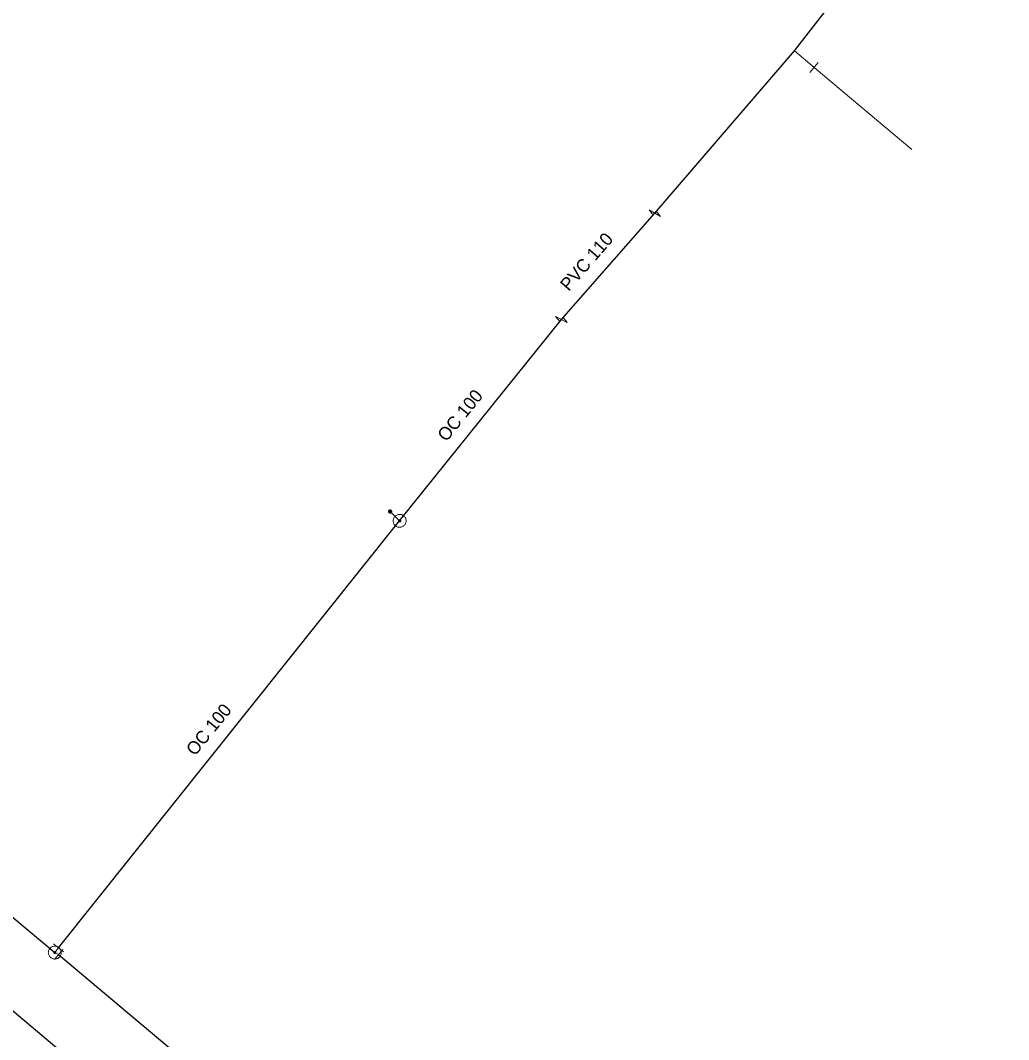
# Model space of a CAD drawing. Extents: x -790267 to -789874, y -989766 to -989454.
# Drawn here: x -790179 to -790102.5, y -989612.1 to -989533.1 of the extents above; entities that cross this region are included whole.
import ezdxf

# ---------------------------------------------------------------- set-up
doc = ezdxf.new("R2010")
doc.units = 0
doc.header["$LTSCALE"] = 0.4
doc.layers.add('1', color=7, linetype='Continuous')
for name, color, linetype, lineweight in [('13', 7, 'Continuous', 13), ('14', 7, 'Continuous', 13), ('17', 7, 'Continuous', 25), ('34', 7, 'Continuous', 13), ('47', 7, 'Continuous', 13), ('9', 7, 'Continuous', 13)]:
    doc.layers.add(name, color=color, linetype=linetype, lineweight=lineweight)

msp = doc.modelspace()

# ---------------------------------------------------------------- linework, layer by layer
at = {"layer": '13'}
msp.add_line((-790117.526, -989536.763), (-790109.967, -989543.114), dxfattribs=at)
at = {"layer": '14'}
for p, q in [((-790119.05, -989535.482), (-790117.526, -989536.763)), ((-790149.607, -989571.88), (-790150.346, -989571.155)), ((-790176.007, -989604.944), (-790176.305, -989605.314)), ((-790176.305, -989605.314), (-790176.006, -989605.454))]:
    msp.add_line(p, q, dxfattribs=at)
at = {"layer": '14', "lineweight": 25}
msp.add_lwpolyline([(-790061.947, -989710.475), (-790095.515, -989680.27), (-790099.671, -989676.98), (-790135.954, -989646.924), (-790158.92, -989627.239), (-790187.694, -989603.019)], dxfattribs=at)
at = {"layer": '17'}
for p, q in [((-790176.007, -989604.944), (-790149.607, -989571.88)), ((-790208.807, -989578.056), (-790176.305, -989605.314))]:
    msp.add_line(p, q, dxfattribs=at)
for points in [[(-790129.848, -989548.061), (-790119.05, -989535.482), (-790055.819, -989454.186)], [(-790149.607, -989571.88), (-790137.084, -989556.289), (-790129.848, -989548.061)], [(-790176.006, -989605.454), (-790166.475, -989613.482), (-790103.748, -989666.305)]]:
    msp.add_lwpolyline(points, dxfattribs=at)
at = {"layer": '34'}
for p, q in [((-790117.204, -989536.379), (-790117.848, -989537.145)), ((-790176.394, -989604.628), (-790175.62, -989605.26)), ((-790176.321, -989605.841), (-790175.689, -989605.067))]:
    msp.add_line(p, q, dxfattribs=at)
at = {"layer": '47'}
for p, q in [((-790130.288, -989547.804), (-790129.98, -989548.211)), ((-790137.535, -989556.052), (-790137.209, -989556.445))]:
    msp.add_line(p, q, dxfattribs=at)
for points in [[(-790130.288, -989547.804), (-790129.407, -989548.317), (-790129.715, -989547.91)], [(-790137.535, -989556.052), (-790136.632, -989556.525), (-790136.958, -989556.132)]]:
    msp.add_lwpolyline(points, dxfattribs=at)
for points in [[(-790149.288, -989571.494), (-790149.33, -989571.463), (-790149.375, -989571.436), (-790149.423, -989571.415), (-790149.472, -989571.398), (-790149.524, -989571.386), (-790149.576, -989571.381), (-790149.628, -989571.381), (-790149.68, -989571.386), (-790149.731, -989571.396), (-790149.781, -989571.411), (-790149.83, -989571.432), (-790149.875, -989571.458), (-790149.917, -989571.488), (-790149.957, -989571.523), (-790149.992, -989571.561), (-790150.023, -989571.603), (-790150.05, -989571.648), (-790150.071, -989571.697), (-790150.088, -989571.745), (-790150.1, -989571.797), (-790150.105, -989571.849), (-790150.106, -989571.902), (-790150.101, -989571.954), (-790150.091, -989572.005), (-790150.075, -989572.054), (-790150.054, -989572.103), (-790150.028, -989572.148), (-790149.998, -989572.19), (-790149.963, -989572.23), (-790149.925, -989572.265), (-790149.883, -989572.296), (-790149.838, -989572.323), (-790149.79, -989572.345), (-790149.741, -989572.361), (-790149.689, -989572.373), (-790149.638, -989572.379), (-790149.585, -989572.38), (-790149.533, -989572.375), (-790149.481, -989572.364), (-790149.432, -989572.348), (-790149.383, -989572.327), (-790149.338, -989572.302), (-790149.296, -989572.271), (-790149.256, -989572.236), (-790149.221, -989572.198), (-790149.19, -989572.156), (-790149.163, -989572.111), (-790149.141, -989572.064), (-790149.125, -989572.014), (-790149.113, -989571.962), (-790149.107, -989571.911), (-790149.107, -989571.859), (-790149.112, -989571.807), (-790149.123, -989571.755), (-790149.138, -989571.705), (-790149.159, -989571.656), (-790149.185, -989571.612), (-790149.215, -989571.569), (-790149.25, -989571.529)], [(-790149.554, -989571.816), (-790149.561, -989571.811), (-790149.569, -989571.807), (-790149.576, -989571.803), (-790149.584, -989571.801), (-790149.593, -989571.799), (-790149.601, -989571.798), (-790149.61, -989571.797), (-790149.619, -989571.798), (-790149.627, -989571.8), (-790149.635, -989571.803), (-790149.643, -989571.806), (-790149.651, -989571.811), (-790149.657, -989571.815), (-790149.664, -989571.82), (-790149.67, -989571.827), (-790149.675, -989571.834), (-790149.679, -989571.842), (-790149.683, -989571.849), (-790149.685, -989571.857), (-790149.687, -989571.866), (-790149.688, -989571.874), (-790149.689, -989571.883), (-790149.688, -989571.892), (-790149.686, -989571.901), (-790149.683, -989571.908), (-790149.68, -989571.916), (-790149.675, -989571.924), (-790149.671, -989571.93), (-790149.666, -989571.937), (-790149.659, -989571.943), (-790149.652, -989571.948), (-790149.644, -989571.952), (-790149.637, -989571.956), (-790149.629, -989571.958), (-790149.62, -989571.96), (-790149.612, -989571.962), (-790149.603, -989571.962), (-790149.594, -989571.961), (-790149.585, -989571.959), (-790149.578, -989571.956), (-790149.57, -989571.953), (-790149.562, -989571.948), (-790149.556, -989571.944), (-790149.549, -989571.939), (-790149.543, -989571.932), (-790149.538, -989571.925), (-790149.534, -989571.917), (-790149.53, -989571.91), (-790149.528, -989571.902), (-790149.526, -989571.893), (-790149.524, -989571.885), (-790149.524, -989571.876), (-790149.525, -989571.867), (-790149.527, -989571.859), (-790149.53, -989571.851), (-790149.533, -989571.843), (-790149.538, -989571.835), (-790149.542, -989571.829), (-790149.547, -989571.822)], [(-790175.917, -989605.63), (-790175.887, -989605.587), (-790175.86, -989605.542), (-790175.839, -989605.495), (-790175.822, -989605.445), (-790175.811, -989605.394), (-790175.806, -989605.341), (-790175.806, -989605.289), (-790175.811, -989605.237), (-790175.821, -989605.186), (-790175.837, -989605.136), (-790175.858, -989605.088), (-790175.885, -989605.043), (-790175.915, -989605), (-790175.95, -989604.961), (-790175.988, -989604.926), (-790176.031, -989604.896), (-790176.076, -989604.869), (-790176.124, -989604.847), (-790176.173, -989604.831), (-790176.224, -989604.82), (-790176.277, -989604.815), (-790176.329, -989604.814), (-790176.382, -989604.82), (-790176.432, -989604.83), (-790176.482, -989604.846), (-790176.53, -989604.867), (-790176.576, -989604.893), (-790176.618, -989604.924), (-790176.657, -989604.959), (-790176.692, -989604.997), (-790176.722, -989605.04), (-790176.749, -989605.085), (-790176.771, -989605.133), (-790176.787, -989605.182), (-790176.798, -989605.233), (-790176.804, -989605.285), (-790176.805, -989605.338), (-790176.799, -989605.39), (-790176.788, -989605.441), (-790176.772, -989605.491), (-790176.751, -989605.539), (-790176.726, -989605.584), (-790176.694, -989605.627), (-790176.659, -989605.666), (-790176.621, -989605.701), (-790176.578, -989605.731), (-790176.533, -989605.758), (-790176.486, -989605.78), (-790176.436, -989605.796), (-790176.385, -989605.807), (-790176.333, -989605.813), (-790176.281, -989605.813), (-790176.229, -989605.808), (-790176.177, -989605.797), (-790176.127, -989605.781), (-790176.079, -989605.76), (-790176.035, -989605.734), (-790175.991, -989605.703), (-790175.952, -989605.668)], [(-790176.241, -989605.365), (-790176.235, -989605.358), (-790176.232, -989605.351), (-790176.228, -989605.343), (-790176.226, -989605.335), (-790176.224, -989605.327), (-790176.223, -989605.318), (-790176.222, -989605.309), (-790176.223, -989605.301), (-790176.226, -989605.293), (-790176.228, -989605.284), (-790176.232, -989605.276), (-790176.236, -989605.269), (-790176.241, -989605.262), (-790176.246, -989605.256), (-790176.253, -989605.25), (-790176.26, -989605.244), (-790176.267, -989605.241), (-790176.275, -989605.237), (-790176.283, -989605.235), (-790176.291, -989605.233), (-790176.3, -989605.232), (-790176.309, -989605.231), (-790176.317, -989605.232), (-790176.326, -989605.234), (-790176.334, -989605.237), (-790176.342, -989605.241), (-790176.349, -989605.245), (-790176.356, -989605.25), (-790176.362, -989605.255), (-790176.368, -989605.262), (-790176.374, -989605.269), (-790176.377, -989605.276), (-790176.381, -989605.284), (-790176.383, -989605.292), (-790176.385, -989605.3), (-790176.387, -989605.308), (-790176.387, -989605.318), (-790176.386, -989605.326), (-790176.384, -989605.335), (-790176.381, -989605.343), (-790176.377, -989605.351), (-790176.373, -989605.358), (-790176.368, -989605.365), (-790176.363, -989605.371), (-790176.356, -989605.377), (-790176.349, -989605.383), (-790176.342, -989605.386), (-790176.334, -989605.39), (-790176.326, -989605.392), (-790176.318, -989605.394), (-790176.31, -989605.396), (-790176.3, -989605.396), (-790176.292, -989605.395), (-790176.284, -989605.392), (-790176.275, -989605.39), (-790176.267, -989605.386), (-790176.26, -989605.382), (-790176.253, -989605.377), (-790176.247, -989605.372)]]:
    msp.add_lwpolyline(points, close=True, dxfattribs=at)
at = {"layer": '9'}
for points in [[(-790150.472, -989571.155), (-790150.472, -989571.168), (-790150.47, -989571.181), (-790150.467, -989571.194), (-790150.462, -989571.206), (-790150.456, -989571.218), (-790150.449, -989571.229), (-790150.441, -989571.239), (-790150.431, -989571.249), (-790150.421, -989571.257), (-790150.41, -989571.264), (-790150.398, -989571.27), (-790150.386, -989571.275), (-790150.373, -989571.278), (-790150.36, -989571.28), (-790150.347, -989571.282), (-790150.334, -989571.281), (-790150.321, -989571.279), (-790150.308, -989571.276), (-790150.296, -989571.271), (-790150.284, -989571.265), (-790150.273, -989571.258), (-790150.263, -989571.25), (-790150.253, -989571.24), (-790150.245, -989571.23), (-790150.238, -989571.219), (-790150.232, -989571.207), (-790150.227, -989571.195), (-790150.224, -989571.182), (-790150.222, -989571.169), (-790150.22, -989571.156), (-790150.221, -989571.143), (-790150.223, -989571.13), (-790150.226, -989571.117), (-790150.231, -989571.105), (-790150.237, -989571.093), (-790150.244, -989571.082), (-790150.252, -989571.072), (-790150.262, -989571.062), (-790150.272, -989571.054), (-790150.283, -989571.047), (-790150.295, -989571.041), (-790150.307, -989571.036), (-790150.32, -989571.033), (-790150.333, -989571.031), (-790150.346, -989571.03), (-790150.359, -989571.03), (-790150.372, -989571.032), (-790150.385, -989571.035), (-790150.397, -989571.04), (-790150.409, -989571.046), (-790150.42, -989571.053), (-790150.43, -989571.061), (-790150.44, -989571.071), (-790150.448, -989571.081), (-790150.455, -989571.092), (-790150.461, -989571.104), (-790150.466, -989571.116), (-790150.469, -989571.129), (-790150.471, -989571.142)], [(-790150.452, -989571.155), (-790150.453, -989571.166), (-790150.451, -989571.177), (-790150.448, -989571.188), (-790150.444, -989571.198), (-790150.439, -989571.208), (-790150.433, -989571.217), (-790150.426, -989571.226), (-790150.418, -989571.234), (-790150.409, -989571.241), (-790150.4, -989571.247), (-790150.39, -989571.252), (-790150.38, -989571.256), (-790150.369, -989571.259), (-790150.358, -989571.262), (-790150.347, -989571.262), (-790150.336, -989571.262), (-790150.325, -989571.26), (-790150.314, -989571.257), (-790150.304, -989571.253), (-790150.294, -989571.248), (-790150.285, -989571.242), (-790150.276, -989571.235), (-790150.268, -989571.227), (-790150.261, -989571.218), (-790150.255, -989571.209), (-790150.25, -989571.199), (-790150.246, -989571.189), (-790150.243, -989571.178), (-790150.241, -989571.167), (-790150.24, -989571.156), (-790150.24, -989571.145), (-790150.242, -989571.134), (-790150.245, -989571.123), (-790150.249, -989571.113), (-790150.254, -989571.103), (-790150.26, -989571.094), (-790150.267, -989571.085), (-790150.275, -989571.077), (-790150.284, -989571.07), (-790150.293, -989571.064), (-790150.303, -989571.059), (-790150.313, -989571.055), (-790150.324, -989571.052), (-790150.335, -989571.05), (-790150.346, -989571.05), (-790150.357, -989571.049), (-790150.368, -989571.051), (-790150.379, -989571.054), (-790150.389, -989571.058), (-790150.399, -989571.063), (-790150.408, -989571.069), (-790150.417, -989571.076), (-790150.425, -989571.084), (-790150.432, -989571.093), (-790150.438, -989571.102), (-790150.443, -989571.112), (-790150.447, -989571.122), (-790150.45, -989571.133), (-790150.452, -989571.144)], [(-790150.433, -989571.155), (-790150.433, -989571.164), (-790150.432, -989571.173), (-790150.429, -989571.182), (-790150.426, -989571.19), (-790150.422, -989571.198), (-790150.417, -989571.206), (-790150.411, -989571.213), (-790150.405, -989571.219), (-790150.398, -989571.225), (-790150.39, -989571.23), (-790150.382, -989571.234), (-790150.374, -989571.237), (-790150.365, -989571.24), (-790150.356, -989571.241), (-790150.347, -989571.243), (-790150.338, -989571.242), (-790150.329, -989571.241), (-790150.32, -989571.238), (-790150.312, -989571.235), (-790150.304, -989571.231), (-790150.296, -989571.226), (-790150.289, -989571.22), (-790150.283, -989571.214), (-790150.277, -989571.207), (-790150.272, -989571.199), (-790150.268, -989571.191), (-790150.265, -989571.183), (-790150.262, -989571.174), (-790150.261, -989571.165), (-790150.259, -989571.156), (-790150.26, -989571.147), (-790150.261, -989571.138), (-790150.264, -989571.129), (-790150.267, -989571.121), (-790150.271, -989571.113), (-790150.276, -989571.105), (-790150.282, -989571.098), (-790150.288, -989571.092), (-790150.295, -989571.086), (-790150.303, -989571.081), (-790150.311, -989571.077), (-790150.319, -989571.074), (-790150.328, -989571.071), (-790150.337, -989571.07), (-790150.346, -989571.069), (-790150.355, -989571.069), (-790150.364, -989571.07), (-790150.373, -989571.073), (-790150.381, -989571.076), (-790150.389, -989571.08), (-790150.397, -989571.085), (-790150.404, -989571.091), (-790150.41, -989571.097), (-790150.416, -989571.104), (-790150.421, -989571.112), (-790150.425, -989571.12), (-790150.428, -989571.128), (-790150.431, -989571.137), (-790150.432, -989571.146)], [(-790150.413, -989571.155), (-790150.413, -989571.162), (-790150.412, -989571.169), (-790150.411, -989571.176), (-790150.408, -989571.182), (-790150.405, -989571.188), (-790150.401, -989571.194), (-790150.397, -989571.2), (-790150.392, -989571.205), (-790150.386, -989571.209), (-790150.38, -989571.213), (-790150.374, -989571.216), (-790150.368, -989571.219), (-790150.361, -989571.22), (-790150.354, -989571.223), (-790150.347, -989571.223), (-790150.34, -989571.223), (-790150.333, -989571.221), (-790150.326, -989571.22), (-790150.32, -989571.217), (-790150.313, -989571.214), (-790150.308, -989571.21), (-790150.302, -989571.206), (-790150.297, -989571.201), (-790150.293, -989571.195), (-790150.289, -989571.189), (-790150.286, -989571.183), (-790150.283, -989571.177), (-790150.281, -989571.17), (-790150.28, -989571.163), (-790150.279, -989571.156), (-790150.279, -989571.149), (-790150.28, -989571.142), (-790150.282, -989571.135), (-790150.285, -989571.129), (-790150.288, -989571.122), (-790150.292, -989571.117), (-790150.296, -989571.111), (-790150.301, -989571.106), (-790150.307, -989571.102), (-790150.312, -989571.098), (-790150.319, -989571.095), (-790150.325, -989571.092), (-790150.332, -989571.09), (-790150.339, -989571.089), (-790150.346, -989571.089), (-790150.353, -989571.089), (-790150.36, -989571.089), (-790150.367, -989571.091), (-790150.373, -989571.094), (-790150.379, -989571.097), (-790150.385, -989571.101), (-790150.391, -989571.105), (-790150.396, -989571.11), (-790150.4, -989571.116), (-790150.404, -989571.121), (-790150.407, -989571.128), (-790150.41, -989571.134), (-790150.411, -989571.141), (-790150.413, -989571.148)], [(-790150.393, -989571.155), (-790150.393, -989571.16), (-790150.393, -989571.165), (-790150.392, -989571.17), (-790150.39, -989571.174), (-790150.388, -989571.179), (-790150.385, -989571.183), (-790150.382, -989571.186), (-790150.378, -989571.19), (-790150.375, -989571.193), (-790150.371, -989571.196), (-790150.366, -989571.198), (-790150.362, -989571.2), (-790150.357, -989571.201), (-790150.352, -989571.203), (-790150.347, -989571.203), (-790150.342, -989571.203), (-790150.337, -989571.202), (-790150.332, -989571.201), (-790150.328, -989571.199), (-790150.323, -989571.197), (-790150.319, -989571.194), (-790150.315, -989571.191), (-790150.312, -989571.187), (-790150.309, -989571.184), (-790150.306, -989571.18), (-790150.304, -989571.175), (-790150.302, -989571.171), (-790150.301, -989571.166), (-790150.3, -989571.161), (-790150.299, -989571.156), (-790150.299, -989571.151), (-790150.3, -989571.146), (-790150.301, -989571.141), (-790150.303, -989571.137), (-790150.305, -989571.132), (-790150.308, -989571.128), (-790150.311, -989571.124), (-790150.314, -989571.121), (-790150.318, -989571.118), (-790150.322, -989571.115), (-790150.327, -989571.113), (-790150.331, -989571.111), (-790150.336, -989571.11), (-790150.341, -989571.109), (-790150.346, -989571.109), (-790150.351, -989571.109), (-790150.356, -989571.11), (-790150.361, -989571.11), (-790150.365, -989571.112), (-790150.37, -989571.114), (-790150.374, -989571.117), (-790150.377, -989571.12), (-790150.381, -989571.123), (-790150.384, -989571.127), (-790150.387, -989571.131), (-790150.389, -989571.136), (-790150.391, -989571.14), (-790150.392, -989571.145), (-790150.393, -989571.15)], [(-790150.373, -989571.155), (-790150.373, -989571.158), (-790150.374, -989571.161), (-790150.373, -989571.163), (-790150.372, -989571.166), (-790150.371, -989571.169), (-790150.369, -989571.171), (-790150.367, -989571.173), (-790150.365, -989571.175), (-790150.363, -989571.177), (-790150.361, -989571.179), (-790150.358, -989571.181), (-790150.355, -989571.182), (-790150.353, -989571.182), (-790150.35, -989571.183), (-790150.347, -989571.183), (-790150.344, -989571.183), (-790150.341, -989571.183), (-790150.338, -989571.182), (-790150.336, -989571.181), (-790150.333, -989571.18), (-790150.331, -989571.178), (-790150.328, -989571.176), (-790150.326, -989571.174), (-790150.325, -989571.172), (-790150.323, -989571.17), (-790150.322, -989571.167), (-790150.32, -989571.164), (-790150.32, -989571.162), (-790150.319, -989571.159), (-790150.318, -989571.156), (-790150.319, -989571.153), (-790150.319, -989571.15), (-790150.32, -989571.147), (-790150.321, -989571.145), (-790150.322, -989571.142), (-790150.324, -989571.14), (-790150.325, -989571.137), (-790150.327, -989571.135), (-790150.33, -989571.134), (-790150.332, -989571.132), (-790150.335, -989571.131), (-790150.337, -989571.13), (-790150.34, -989571.129), (-790150.343, -989571.129), (-790150.346, -989571.128), (-790150.349, -989571.129), (-790150.352, -989571.128), (-790150.354, -989571.13), (-790150.357, -989571.13), (-790150.36, -989571.131), (-790150.362, -989571.133), (-790150.364, -989571.134), (-790150.366, -989571.136), (-790150.368, -989571.139), (-790150.37, -989571.141), (-790150.371, -989571.144), (-790150.372, -989571.146), (-790150.373, -989571.149), (-790150.373, -989571.152)], [(-790150.354, -989571.155), (-790150.354, -989571.157), (-790150.354, -989571.157), (-790150.353, -989571.157), (-790150.353, -989571.159), (-790150.354, -989571.16), (-790150.352, -989571.16), (-790150.352, -989571.16), (-790150.352, -989571.162), (-790150.352, -989571.162), (-790150.351, -989571.163), (-790150.349, -989571.163), (-790150.349, -989571.163), (-790150.349, -989571.164), (-790150.347, -989571.164), (-790150.347, -989571.164), (-790150.346, -989571.164), (-790150.345, -989571.164), (-790150.345, -989571.163), (-790150.344, -989571.163), (-790150.342, -989571.163), (-790150.342, -989571.162), (-790150.342, -989571.162), (-790150.341, -989571.161), (-790150.341, -989571.161), (-790150.339, -989571.16), (-790150.339, -989571.159), (-790150.338, -989571.158), (-790150.338, -989571.158), (-790150.338, -989571.157), (-790150.338, -989571.156), (-790150.338, -989571.155), (-790150.338, -989571.154), (-790150.338, -989571.154), (-790150.339, -989571.153), (-790150.339, -989571.152), (-790150.34, -989571.151), (-790150.34, -989571.151), (-790150.341, -989571.15), (-790150.341, -989571.15), (-790150.342, -989571.149), (-790150.343, -989571.149), (-790150.344, -989571.148), (-790150.344, -989571.148), (-790150.345, -989571.148), (-790150.346, -989571.148), (-790150.347, -989571.148), (-790150.348, -989571.148), (-790150.348, -989571.148), (-790150.349, -989571.149), (-790150.35, -989571.148), (-790150.351, -989571.15), (-790150.351, -989571.15), (-790150.352, -989571.15), (-790150.352, -989571.15), (-790150.353, -989571.152), (-790150.353, -989571.153), (-790150.353, -989571.154), (-790150.354, -989571.154), (-790150.354, -989571.155)]]:
    msp.add_lwpolyline(points, close=True, dxfattribs=at)

# ---------------------------------------------------------------- texts
at = {"layer": '1'}
for s, rotation, p in [('PVC 110 ', 49, (-790136.517, -989554.152)), ('OC 100', 51, (-790145.992, -989565.806)), ('OC 100', 51, (-790165.449, -989590.142))]:
    msp.add_text(s, height=1, rotation=rotation, dxfattribs=at).set_placement(p)

doc.saveas('drawing.dxf')
